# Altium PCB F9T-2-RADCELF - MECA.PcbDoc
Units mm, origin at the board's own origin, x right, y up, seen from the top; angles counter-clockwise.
Board outline 67.17 x 37.33 mm, 2 copper layers (Top Layer, Bottom Layer), stack 1.581 mm thick; 16 components, 11 nets, 196 pads, 132 vias.
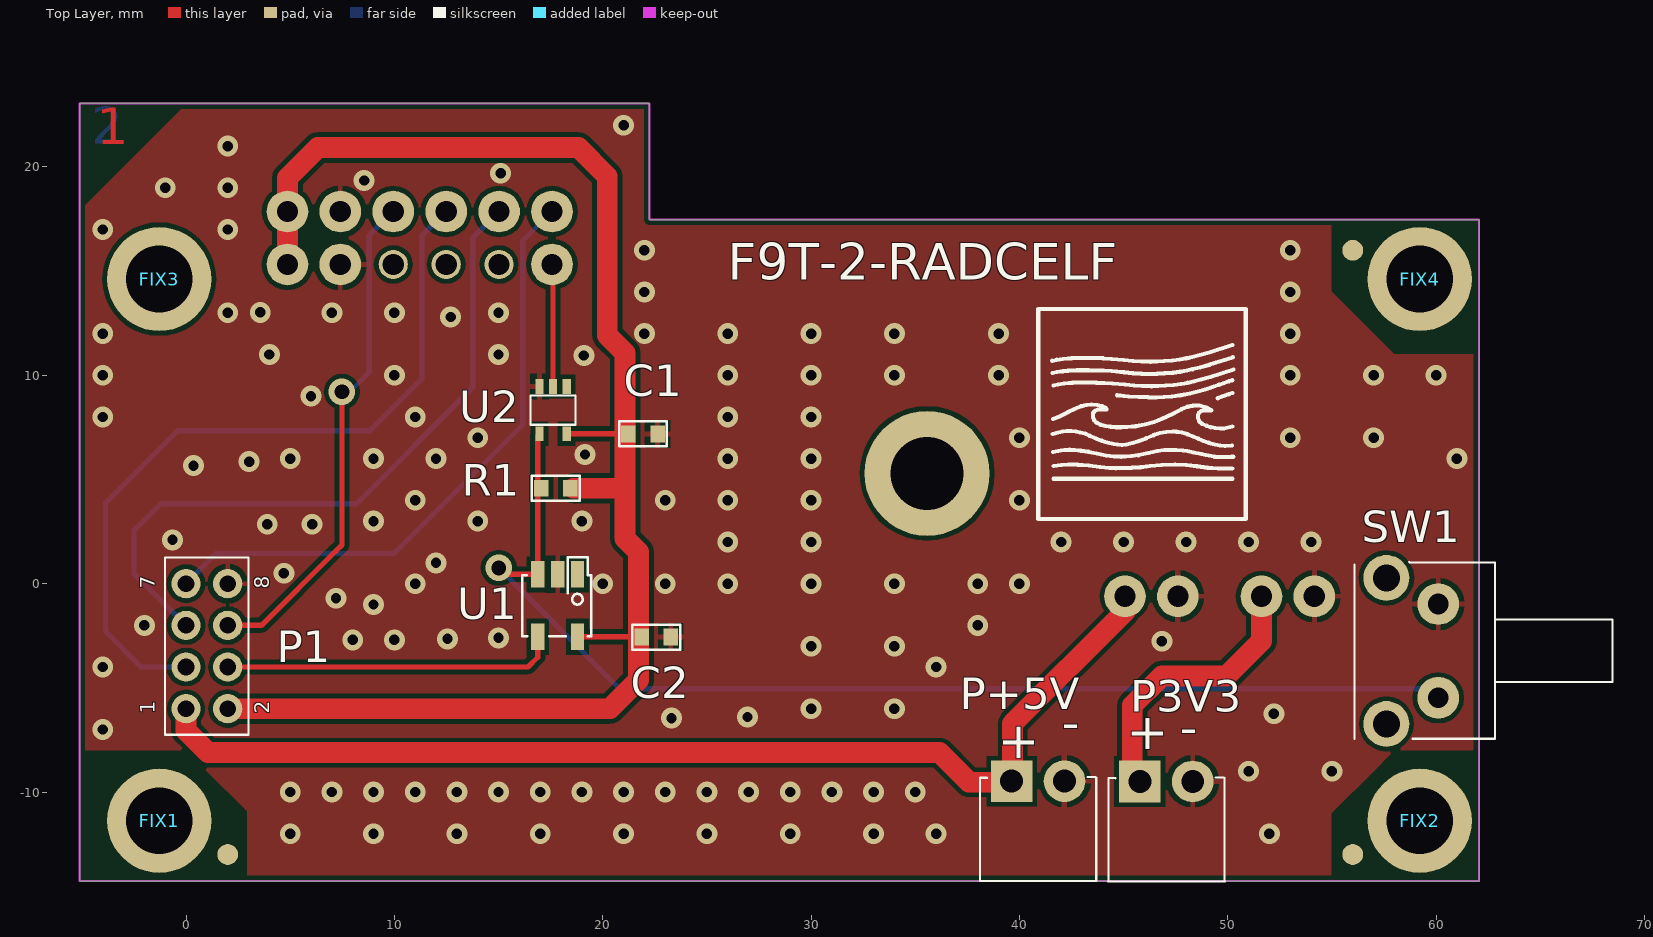
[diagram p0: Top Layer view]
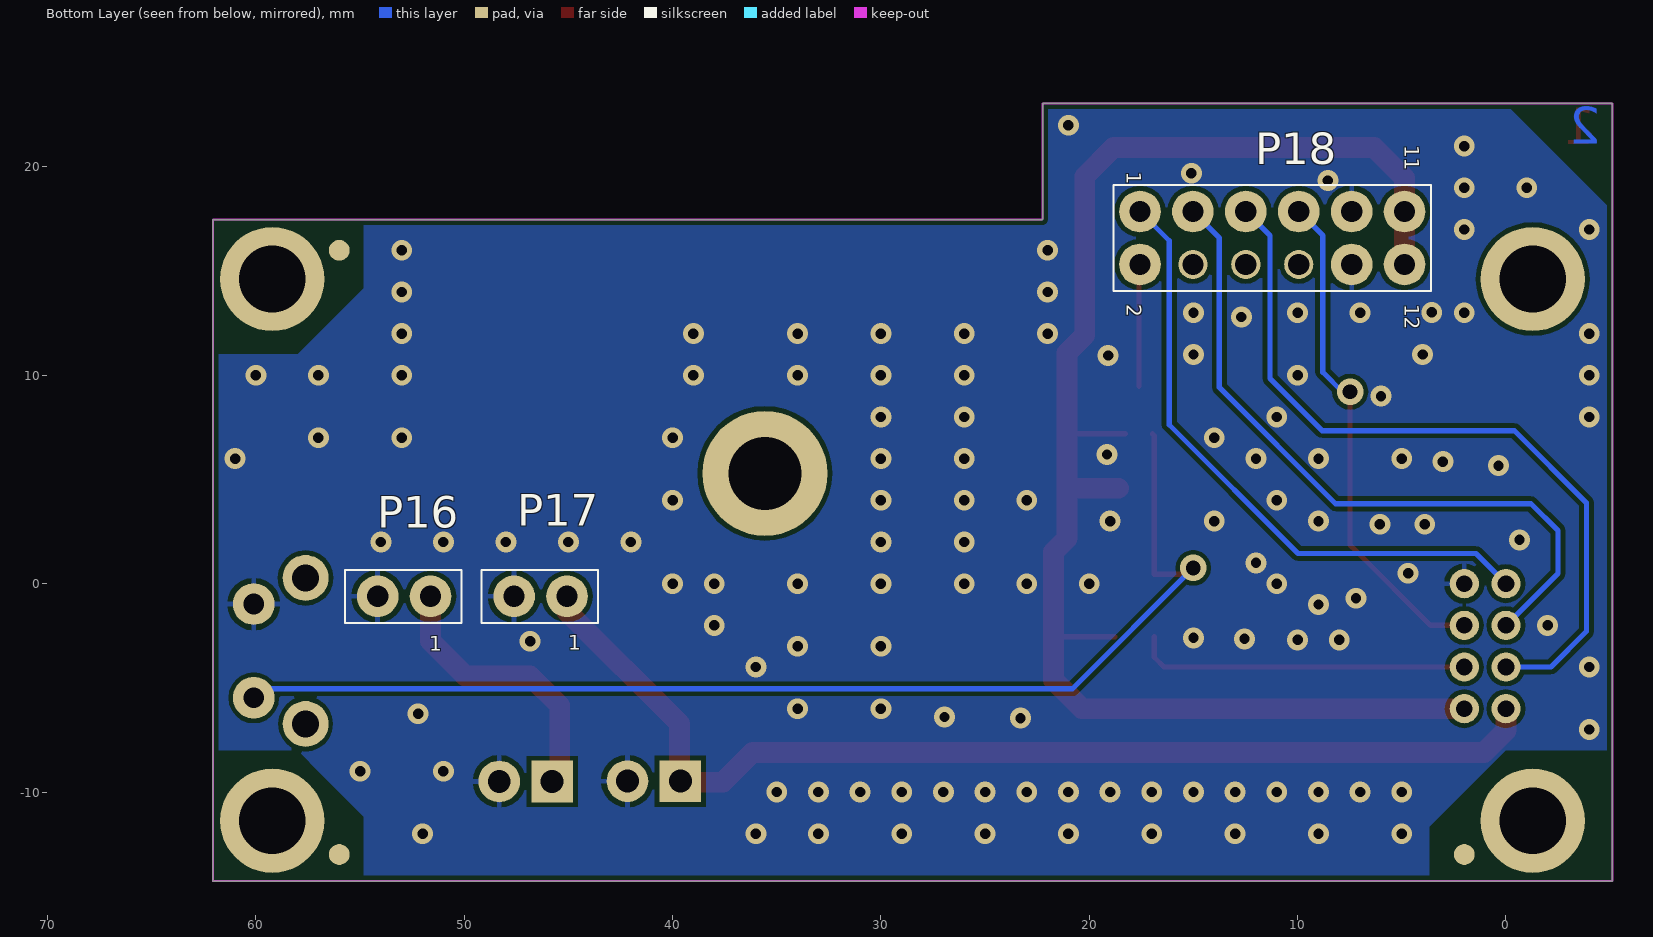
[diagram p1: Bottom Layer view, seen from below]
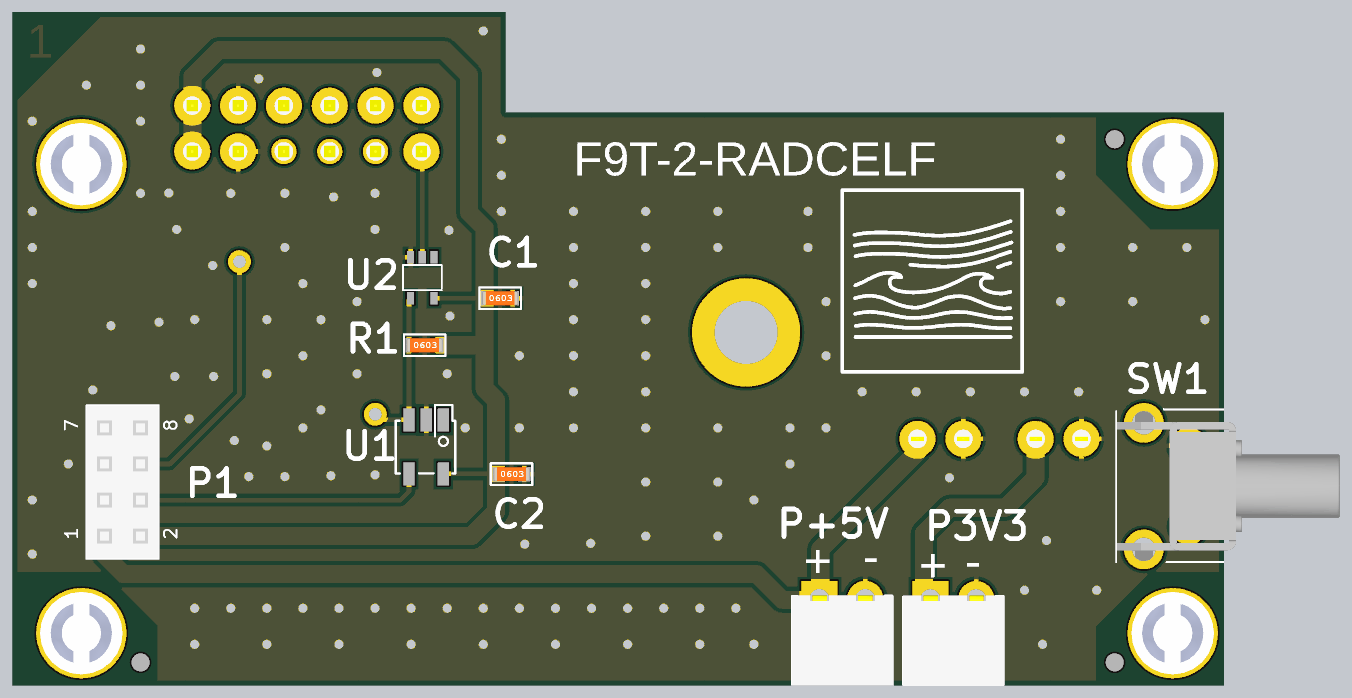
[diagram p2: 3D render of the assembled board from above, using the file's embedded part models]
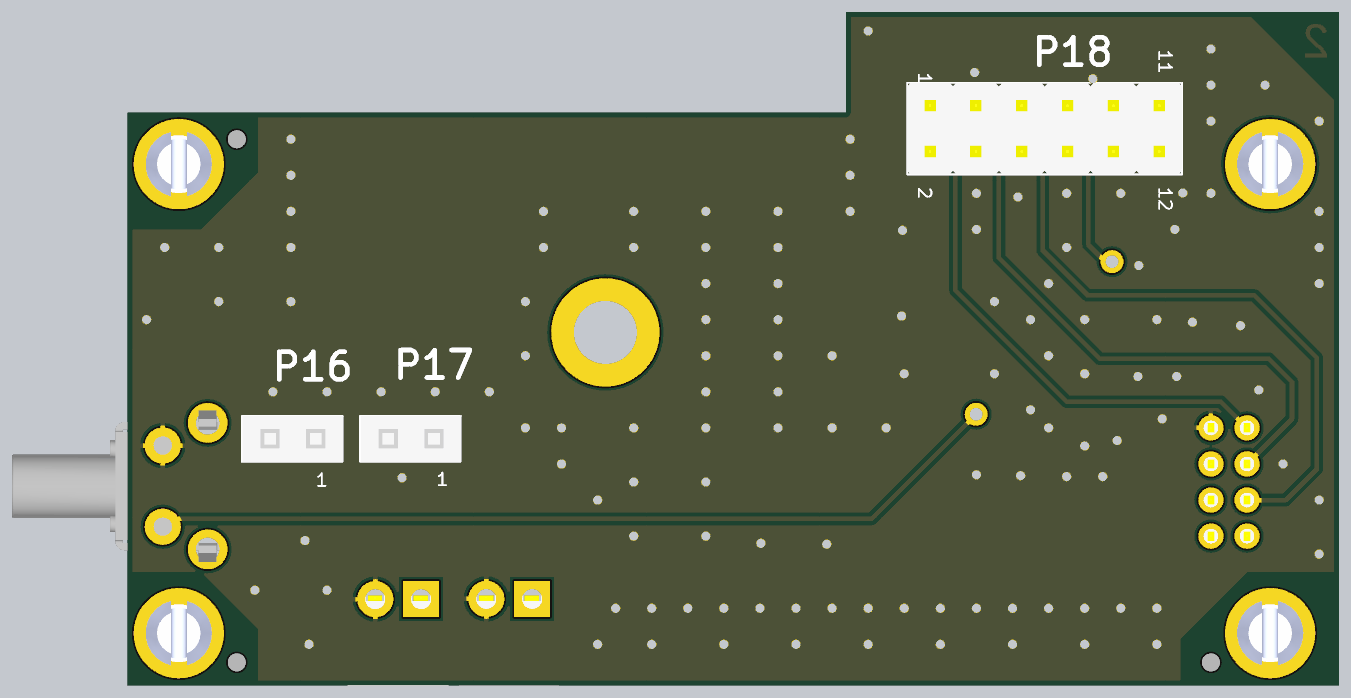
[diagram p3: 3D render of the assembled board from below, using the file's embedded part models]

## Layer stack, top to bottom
Top Solder: solder mask 0.0102, Solder Resist, Dk 3.5
Top Layer: signal copper 0.0356
Dielectric 1: dielectric 1.51, FR-4, Dk 4.8
Bottom Layer: signal copper 0.0356
Bottom Solder: solder mask 0.0102, Solder Resist, Dk 3.5

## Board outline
-5.107,-14.276 -5.107,23.049 22.242,23.049 22.242,17.49 22.259,17.473 62.067,17.473 62.067,-14.276

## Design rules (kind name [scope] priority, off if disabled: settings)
Clearance Clearance_1 [All] p1: gap=0.22 ignorepadtopadclearanceinfootprint=FALSE except(0: Arc-Hole Track-Hole SMDPad-Hole THPad-Hole Via-Hole Fill-Hole Poly-Hole Region-Hole Text-Hole)
Clearance [OnLayer('Keep-Out Layer')] p2: gap=0.4 ignorepadtopadclearanceinfootprint=FALSE except(0: Arc-Hole Track-Hole SMDPad-Hole THPad-Hole Via-Hole Fill-Hole Poly-Hole Region-Hole Text-Hole)
ComponentClearance [All] p1 off: gap=0.254 collisioncheckmode=3 verticalgap=0.254 showdistances=FALSE
Height [All] p1 off: minheight=0 maxheight=25.4 prefheight=12.7
HoleSize [All] p1: absolutevalues=TRUE maxlimit=10 minlimit=0.025 maxpercent=80.000 minpercent=20.000
MinimumSolderMaskSliver [All] p1 off: minsoldermaskwidth=0.254
PolygonConnect PolygonConnect_1 [IsVia] p1: connectstyle=Direct reliefconductorwidth=0.254 reliefentries=4 polygonreliefangle="90 Angle" airgapwidth=0.254
PolygonConnect [All] p2: connectstyle=Relief reliefconductorwidth=0.254 reliefentries=4 polygonreliefangle="90 Angle" airgapwidth=0.254
RoutingVias [All] p1: holewidth=0.711 width=1.27 viastyle="Through Hole" minholewidth=0.3 minwidth=0.7 maxholewidth=0.711 maxwidth=1.27
SilkToBoardRegionClearance [All] p1 off:
SilkToSilkClearance [All] p1 off: silktosilkclearance=0.254
SilkToSolderMaskClearance [IsPad] p1 off: minsilkscreentomaskgap=0.254 clearancetoexposedcopper=TRUE
SolderMaskExpansion [All] p1: expansion=0.102
Width [All] p1: maxlimit=10 minlimit=0.254 preferedwidth=0.254 minimp=50.000000 maximp=50.000000 favimp=50.000000
23 further rules are at their usual default settings.

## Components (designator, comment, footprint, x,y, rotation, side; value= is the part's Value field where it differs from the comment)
C1 "100nF 25V" 0603 21.934,7.187 r0 top
C2 "100nF 25V" 0603 22.566,-2.563 r0 top
FIX1 "8882" 8882 -1.284,-11.38 r0 top
FIX2 "8882" 8882 59.216,-11.38 r0 top
FIX3 "8882" 8882 -1.284,14.62 r0 top
FIX4 "8882" 8882 59.216,14.62 r0 top
P1 "AF1D-200-08-G-H63" AF1D-200-08-G-H63 0,-6 r90 top
P3V3 "AF1C-02-G-H5" AF1C-02-G-H5 45.782,-9.492 r180 top
P16 "" F1D-02-G 51.618,-0.609 r0 bottom
P17 "" F1D-02-G 45.068,-0.609 r0 bottom
P18 "A61-12-7-G" A61-12-7-G 11.217,16.592 r270 bottom locked
P+5V "AF1C-02-G-H5" AF1C-02-G-H5 39.628,-9.48 r180 top
R1 "4.7K" 0603 17.748,4.582 r0 top
SW1 "FSMRA4JH" FSMRA4JH 62.814,-3.229 r90 top
U1 "TPS3837DBV" SOT23-5 18.785,0.446 r270 top
U2 "SN74LVC1G07DCK" SC70-5 18.266,9.463 r180 top

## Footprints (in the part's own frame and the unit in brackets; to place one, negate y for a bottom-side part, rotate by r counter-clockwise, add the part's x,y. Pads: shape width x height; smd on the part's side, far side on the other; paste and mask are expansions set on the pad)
0603 [mm]
  rect 0.7x0.8 smd mask+0.05: 1(-0.7,0) 2(0.7,0)
  silkscreen extent -1.15,-0.6 1.15,0.6, body extent -1,-0.39 1,0.39, height 0.79
8882 [mm]
  round 5 hole 3.2: FIX(0,0)
  body extent -2.29,-2.29 2.29,2.29, height 13.29
A61-12-7-G [mm]
  round 2 hole 1.02: 1(-1.27,-6.35) 2(1.27,-6.35) 3(-1.27,-3.81) 5(-1.27,-1.27) 7(-1.27,1.27) 9(1.27,3.81) 10(-1.27,3.81) 11(1.27,6.35) 12(-1.27,6.35)
  round 1.4 hole 1.02: 4(1.27,-3.81) 6(1.27,-1.27) 8(1.27,1.27)
  silkscreen extent -2.54,-7.62 2.54,7.62, body extent -2.54,-7.62 2.54,7.62, height 9.54
AF1C-02-G-H5 [mm]
  rect 2x2 hole 1.1: 1(0,0)
  round 2 hole 1.1: 2(-2.54,0)
  silkscreen extent -4.08,-0.19 1.53,4.8, body extent -4.08,-0.19 1.5,4.81, height 2.6
AF1D-200-08-G-H63 [mm]
  round 1.4 hole 0.8: 1(0,0) 2(0,-2) 3(2,0) 4(2,-2) 5(4,0) 6(4,-2) 7(6,0) 8(6,-2)
  silkscreen extent -1.25,-3 7.25,1, body extent -1.2,-3 7.2,1, height 6.35
F1D-02-G [mm]
  round 2 hole 1.02: 1(0,0) 2(2.54,0)
  silkscreen extent -1.49,-1.27 4.1,1.27, body extent -1.52,-1.27 4.06,1.27, height 5
FSMRA4JH [mm]
  round 2 hole 1: 1(-2.25,2.71) 2(2.25,2.71)
  round 2.2 hole 1.3: fix(-3.505,5.2) fix(3.505,5.2)
  silkscreen extent -4.21,-5.65 4.27,6.73, body extent -4.2,-5.66 4.2,6.7, height 7
SC70-5 [mm]
  rect 0.4x0.7 smd: 1(0,0) 2(0.65,0) 3(1.3,0) 4(1.3,2.27) 5(0,2.27)
  silkscreen extent -0.43,0.43 1.72,1.83, body extent -0.34,0.1 1.66,2.2, height 0.95
SOT23-5 [mil]
  rect 50x25 smd: 1(0,0) 2(0,-37) 3(0,-75) 4(118,-75) 5(118,0)
  silkscreen extent -33,-104 117,26, body extent 0,-94 110,20, height 57

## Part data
C1 C2: library part CAP, "Capacitor"
FIX1 FIX2 FIX3 FIX4: library part CON1, "Connector"
P1: library part CON8, "Connector"
P3V3 P16 P17 P+5V: library part CON2, "Connector"
P18: library part CON12, "Connector"
R1: library part 0603
SW1: library part BP
U1: "Active-high, push-pull, nano-power supervisors with manual reset"
U2: "Buffer / Driver de ligne, 74LVC1G07, 1.65 V à 5.5 V, SC70-5"

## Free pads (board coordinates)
  rect 0.813x0.813 on Mech16: 1(4.105,11.142) 1(5.629,11.142) 1(8.357,11.192) 1(9.881,11.192) 1(13.454,4.992) 1(14.978,4.992) 1(17.706,5.04) 1(19.23,5.04) 1(20.805,15.49) 1(20.805,16.991) 1(20.805,18.492) 1(22.329,15.49) 1(22.329,16.991) 1(22.329,18.492) 1(22.517,11.779) 1(22.517,13.303) 1(30.005,7.192) 1(30.005,8.69) 1(30.955,15.741) 1(31.529,7.192) 1(31.529,8.69) 1(32.479,15.741) 1(33.955,10.941) 1(35.479,10.941)
  rect 1.499x0.45 on Mech16: 1(4.117,5.317) 1(4.117,5.965) 1(4.117,6.615) 1(4.117,7.265) 1(4.117,7.916) 1(4.117,8.566) 1(4.117,9.216) 1(4.117,9.866) 1(9.919,5.317) 1(9.919,5.965) 1(9.919,6.615) 1(9.919,7.265) 1(9.919,7.916) 1(9.919,8.566) 1(9.919,9.216) 1(9.919,9.866) 1(13.416,6.316) 1(13.416,6.966) 1(13.416,7.616) 1(13.416,8.266) 1(13.416,8.916) 1(13.416,9.567) 1(13.416,10.217) 1(13.416,10.867) 1(19.218,6.316) 1(19.218,6.966) 1(19.218,7.616) 1(19.218,8.266) 1(19.218,8.916) 1(19.218,9.567) 1(19.218,10.217) 1(19.218,10.867)
  rect 1.016x1.999 on Mech16: 1(4.867,13.692) 1(4.867,19.49) 1(7.407,13.692) 1(7.407,19.49) 1(9.947,13.692) 1(9.947,19.49) 1(12.487,13.692) 1(12.487,19.49) 1(15.027,13.692) 1(15.027,19.49) 1(17.567,13.692) 1(17.567,19.49)
  round 0.991 on Mech16: 1(6.137,16.592) 1(11.217,16.592) 1(16.297,16.592)
  rect 1.016x1.016 on Mech16: 1(20.477,20.138) 1(20.477,22.043) 1(26.177,6.938) 1(26.177,8.845)
  rect 1.372x1.016 on Mech16: 1(22.509,21.091) 1(28.209,7.89)
  rect 0.399x0.95 on Mech16: 1(23.967,13.242) 1(23.967,15.442) 1(24.618,13.242) 1(24.618,15.442) 1(25.268,13.242) 1(25.268,15.442) 1(34.066,13.14) 1(34.066,15.34) 1(34.717,13.14) 1(34.717,15.34) 1(35.367,13.14) 1(35.367,15.34)
  round 2.54 on Mech16: 1(26.177,18.901) 1(26.177,23.981) 1(28.717,21.441) 1(31.257,18.901) 1(31.257,23.981) 1(36.276,18.802) 1(36.276,23.882) 1(38.816,21.342) 1(41.356,18.802) 1(41.356,23.882) 1(44.478,18.802) 1(44.478,23.882) 1(47.018,21.342) 1(49.558,18.802) 1(49.558,23.882) 1(52.977,18.802) 1(52.977,23.882) 1(55.517,21.342) 1(58.057,18.802) 1(58.057,23.882)
  rect 1.049x2.2 on Mech16: 1(27.241,12.241) 1(30.193,12.241) 1(37.343,12.142) 1(40.292,12.142) 1(45.542,12.142) 1(48.494,12.142) 1(54.044,12.142) 1(56.993,12.142)
  rect 1.148x1.798 on Mech16: 1(28.567,3.491) 1(31.567,3.491)
  rect 0.998x1.049 on Mech16: 1(28.717,13.765) 1(38.816,13.666) 1(47.018,13.666) 1(55.517,13.666)
  rect 1.016x0.864 on Mech16: 1(28.717,15.531) 1(28.717,16.953) 1(38.816,15.429) 1(38.816,16.851) 1(47.018,15.429) 1(47.018,16.851) 1(55.517,15.429) 1(55.517,16.851)
  round 5.791 on Mech16: 1(35.568,5.292)
  rect 1.524x1.524 on Mech16: 1(45.067,-0.609) 1(51.618,-0.609)
  round 1.524 on Mech16: 1(47.607,-0.609) 1(54.158,-0.609)
  round 3.198 on Mech16: 1(58.567,-0.21)
  round 6 hole 3.5: fix(35.568,5.291)
  round 1 smd mask+0.1: MIRE(2,-13) MIRE(56,-13) MIRE(56,16)
  round 1 smd far side mask+0.1: MIRE(2,-13) MIRE(56,-13) MIRE(56,16)

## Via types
v1: diameter 1, hole 0.5, Top Layer to Bottom Layer, 130 vias
v2: diameter 1.27, hole 0.711, Top Layer to Bottom Layer, 2 vias

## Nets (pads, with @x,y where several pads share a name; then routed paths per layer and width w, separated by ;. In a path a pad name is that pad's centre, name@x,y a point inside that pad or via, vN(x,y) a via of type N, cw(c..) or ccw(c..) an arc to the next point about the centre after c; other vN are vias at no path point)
0VD: C1.2 C2.2 P1.8 P3V3.2 P16.2 P17.2 P18.9 P18.10 P+5V.2 SW1.2 U1.2 U2.3
  other v1: 5,-12 9,-12 13,-12 17,-12 21,-12 25,-12 29,-12 33,-12 36,-12 52,-12 5,-10 7,-10 9,-10 11,-10 13,-10 15,-10 17,-10 19,-10 21,-10 23,-10 25,-10 27,-10 29,-10 31,-10 33,-10 35,-10 51,-9 55,-9 -4,-7 23.3,-6.45 26.95,-6.4 52.218,-6.245 30,-6 34,-6 -4,-4 36,-4 30,-3 34,-3 46.842,-2.765 8,-2.7 10,-2.7 12.55,-2.65 15,-2.6 -2,-2 38,-2 9,-1 7.2,-0.7 11,0 20,0 23,0 26,0 30,0 34,0 38,0 40,0 4.7,0.5 12,1 26,2 30,2 42,2 45,2 48,2 51,2 54,2 -0.65,2.1 3.9,2.85 6.05,2.85 9,3 14,3 19,3 11,4 23,4 26,4 30,4 40,4 0.358,5.666 3.026,5.859 5,6 9,6 12,6 26,6 30,6 61,6 19.15,6.2 14,7 40,7 53,7 57,7 -4,8 11,8 26,8 30,8 6,9 -4,10 10,10 26,10 30,10 34,10 39,10 53,10 57,10 60,10 19.1,10.95 4,11 15,11 -4,12 22,12 26,12 30,12 34,12 39,12 53,12 12.7,12.8 2,13 7,13 10,13 15,13 3.563,13.021 22,14 53,14 22,16 53,16 -4,17 2,17 -1,19 2,19 8.55,19.35 15.1,19.7 2,21 21,22
+3V3: P3V3.1 P16.1 | length 13.3
  Top Layer w1: P3V3.1@45.697,-9.455 45.418,-9.176 45.418,-5.852 46.842,-4.428 49.946,-4.428 51.618,-2.756 P16.1
+5V: P1.1 P17.1 P+5V.1 | length 52.9
  Top Layer w1: P1.1 0,-7.048 1.062,-8.11 36.163,-8.11 37.581,-9.528 39.677,-9.528 39.677,-6.72 45.068,-1.329 P17.1
+V_PMOD: C1.1 C2.1 P1.2 P18.11 P18.12 R1.2 U1.5 U2.5 | length 74
  Top Layer w0.254: U2.5 C1.1@21.077,7.193 ; U1.5 21.704,-2.551 C2.1@21.716,-2.563
  Top Layer w1: P1.2 20.346,-6 21.716,-4.629 21.716,-2.563 21.716,1.523 21.077,2.162 21.077,4.509 ; P18.11 P18.12 4.867,19.477 6.326,20.936 18.833,20.936 20.214,19.555 20.214,11.939 21.077,11.076 21.077,7.193 21.077,4.509 ; R1.2@18.598,4.582 21.005,4.582 21.077,4.509
NetP1_4: P1.4 U1.4 | length 16.1
  Top Layer w0.254: P1.4 16.409,-4 16.88,-3.529 U1.4
NetP18_2: P18.2 U2.2 | length 5.9
  Top Layer w0.254: P18.2 17.616,15.272 U2.2
NetR1_1: R1.1 SW1.1 U1.3 U2.4 | length 56.4
  Top Layer w0.254: v2(15.015,0.754) 15.323,0.446 U1.3 16.88,7.106 U2.4
  Bottom Layer w0.254: v2(15.015,0.754) 20.816,-5.046 59.672,-5.046 SW1.1
RXD: P1.5 P18.3 | length 33.6
  Bottom Layer w0.254: P1.5 -2.494,0.494 -2.494,2.544 -1.2,3.837 8.174,3.837 13.755,9.419 13.755,16.59 P18.3
TP1: P1.6 P18.7 | length 24.3
  Top Layer w0.254: P1.6 3.625,-2 7.185,1.56 7.483,1.858 v2(7.483,9.213)
  Bottom Layer w0.254: v2(7.483,9.213) 7.857,9.213 8.79,10.147 8.79,16.705 P18.7
TP2: P1.7 P18.1 | length 30.1
  Bottom Layer w0.254: P1.7 1.448,1.448 9.985,1.448 16.164,7.627 16.164,16.459 P18.1
TXD: P1.3 P18.5 | length 36.9
  Bottom Layer w0.254: P1.3 -2.152,-4 -3.867,-2.286 -3.867,3.878 -0.398,7.347 8.827,7.347 11.329,9.848 11.329,16.704 P18.5
pads on no net: FIX1.FIX FIX2.FIX FIX3.FIX FIX4.FIX P18.4 P18.6 P18.8 SW1.fix U1.1 U2.1

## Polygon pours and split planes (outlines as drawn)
0VD on Bottom Layer "Bottom Layer-No Net" (solid, remove dead copper, pour order 0): -7,-8 0,-8 3.675,-11.675 3.675,-15 54.824,-15 54.824,-11.176 57,-9 58,-8 60,-8 62,-8 62,11 61,11 58,11 54.824,14.176 54.824,18 23,18 23,19 23,24 22,24 1,24 -6,17
0VD on Top Layer "Bottom Layer-No Net" (solid, remove dead copper, pour order 2): -7,-8 0,-8 2.928,-10.928 2.928,-15 54.973,-15 54.973,-11.027 57,-9 58,-8 60,-8 62,-8 62,11 61,11 58,11 54.973,14.027 54.973,18 23,18 23,19 23,24 22,24 1,24 -6,17

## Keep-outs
Keep-Out Layer:
  the board outline again, w0.1

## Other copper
Top Layer:
  text "1" at -4.296,20.526 h3
Bottom Layer:
  text "2" at -4.557,20.544 h3

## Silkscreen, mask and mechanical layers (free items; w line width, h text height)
Top Overlay:
  drawing of 222 lines, arcs and shapes, not listed
  text "F9T-2-RADCELF" at 26,14 h3
  text "+" at 38.653,-6.628 h3 r270
  text "-" at 42.041,-8.042 h3
  text "-" at 47.705,-8.289 h3
  text "+" at 45.152,-8.526 h3
Mechanical 1:
  text "1" at 18.744,19.227 h1.52
  text "11" at 2.112,19.152 h1.52
  text "2" at 18.857,14.11 h1.52
  text "12" at 1.661,12.529 h1.52
  text "2" at 53.852,1.09 h1.52
  text "2" at 47.417,0.94 h1.52
  text "1" at 44.633,0.789 h1.52
  text "1" at 51.255,0.752 h1.52
  text "2" at 4.991,-6.379 h1.52
  text "1" at -4.153,-6.492 h1.52
Mechanical 3:
  drawing of 955 lines, arcs and shapes, not listed
Mechanical 14:
  drawing of 534 lines, arcs and shapes, not listed
Mechanical 30:
  lines w0.05: 54.158,-0.609 54.158,-0.084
